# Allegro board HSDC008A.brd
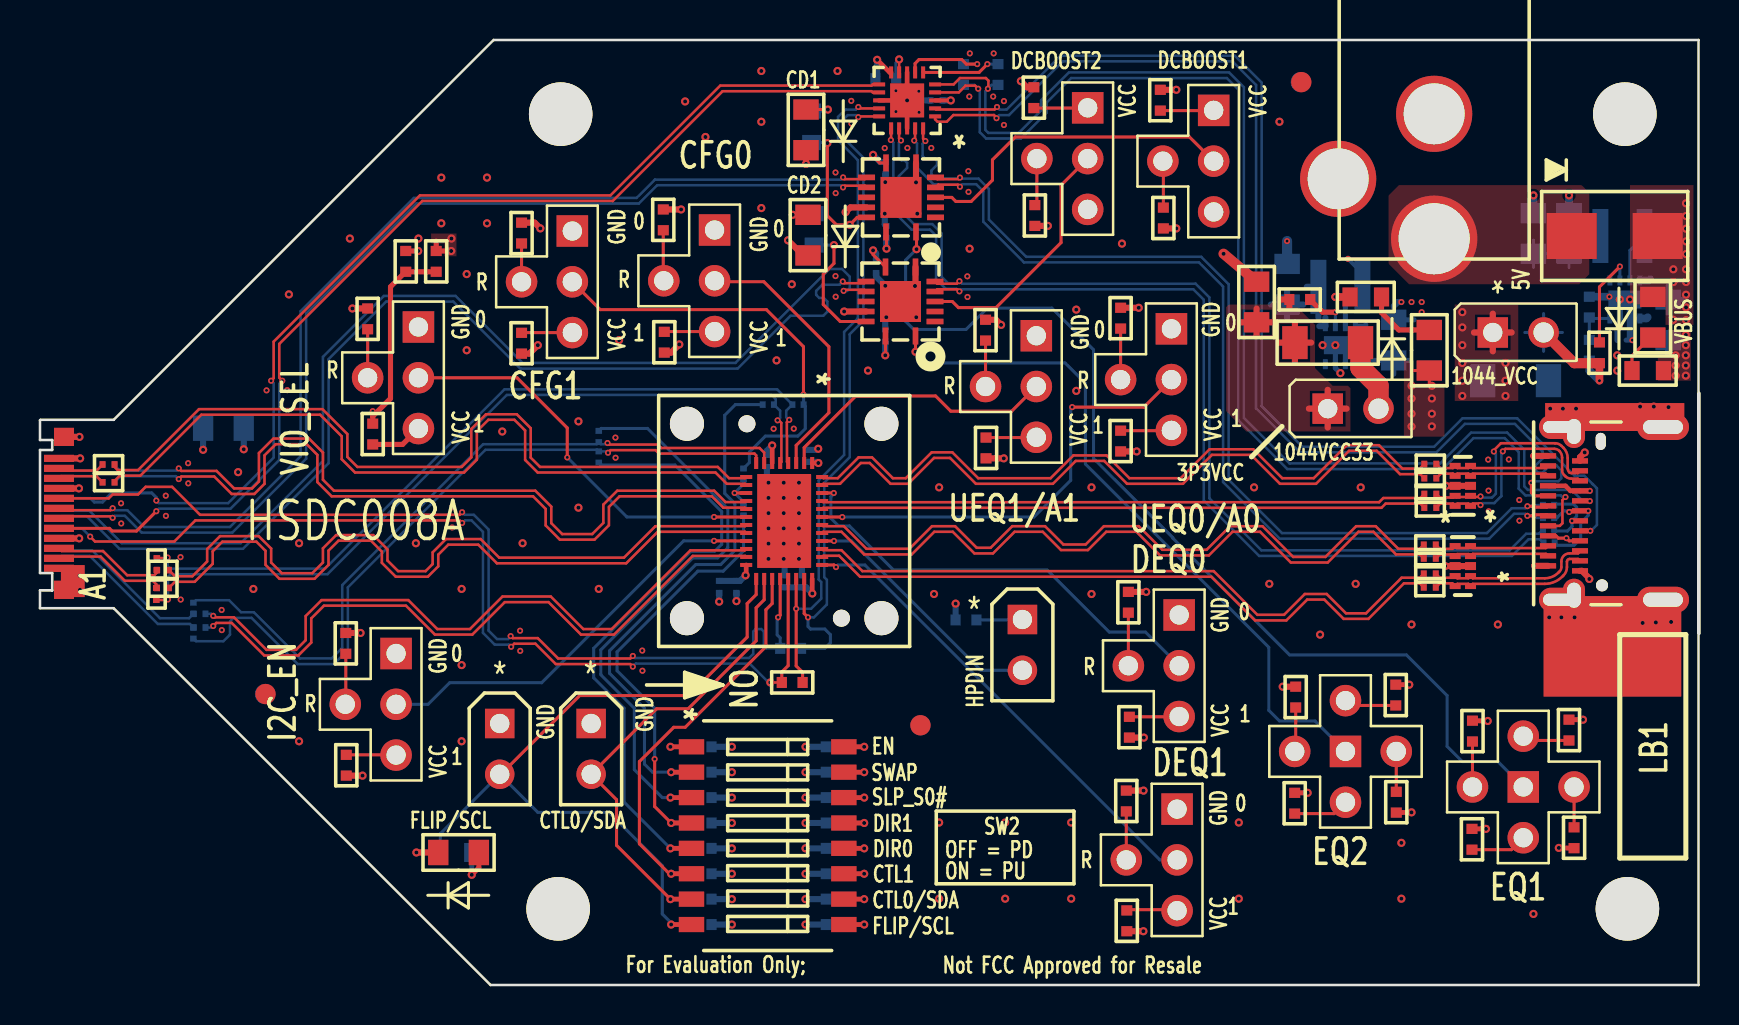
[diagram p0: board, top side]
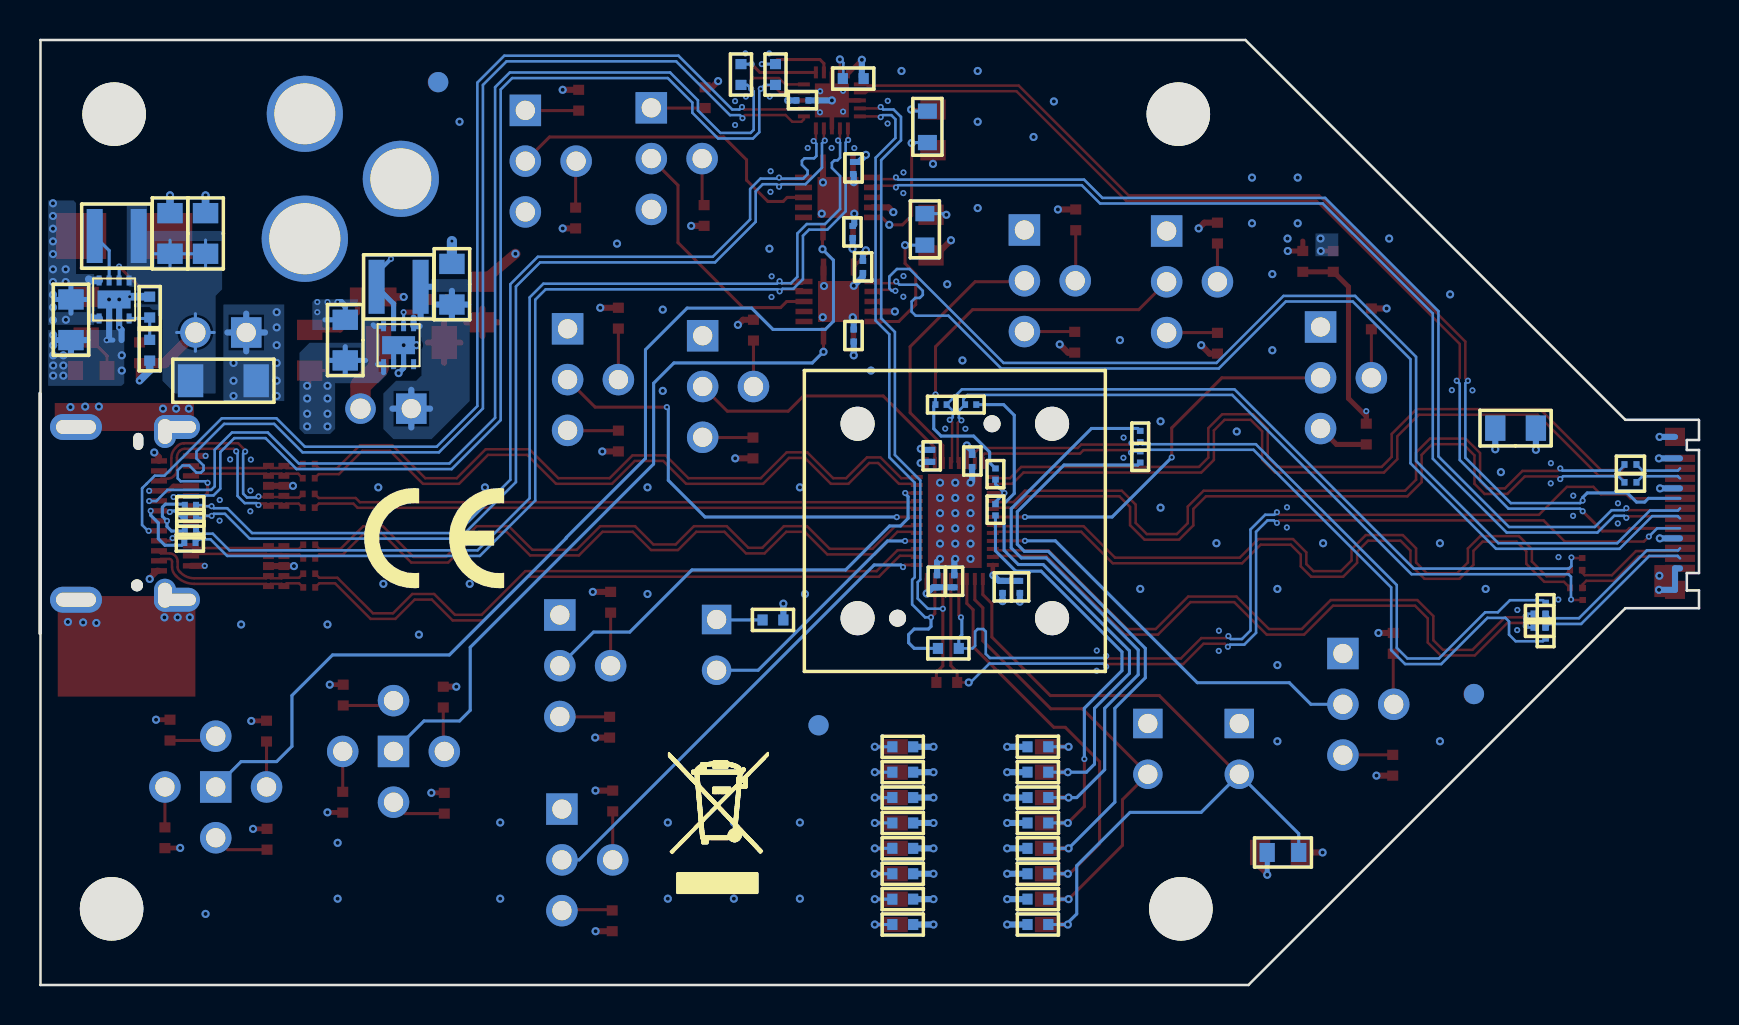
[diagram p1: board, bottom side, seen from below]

Outline 82.95 x 47.27 mm; copper layers: TOP, L2_GND, L3_PWR, L4_PWR, L5_GND, BOTTOM. Coordinates in mm from the lower left corner of the outline.
Outline path: 0,28.24 0.03,28.27 3.68,28.27 22.68,47.27 82.93,47.27 82.93,0 22.53,0 3.68,18.85 0,18.85 0,19.74 0.61,19.74 0.61,19.74 0.61,20.6 0.6,20.61 0,20.61 0,26.76 0.6,26.76 0.61,26.77 0.61,27.25 0.6,27.26 0,27.26 0,28.24

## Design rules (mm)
net group DIFFPAIR0: nets URX2N URX2P
net group DIFFPAIR1: nets UTX1N UTX1P
net group DIFFPAIR2: nets UTX2N UTX2P
net group DIFFPAIR3: nets URX1N URX1P
net group DIFFPAIR4: nets N48836 N48840
net group DIFFPAIR5: nets N48852 N48856
net group DIFFPAIR6: nets N48828 N48832
net group DIFFPAIR7: nets N48844 N48848
net group DIFFPAIR8: nets C_DRX2N C_DRX2P
net group DIFFPAIR9: nets C_DTX2N C_DTX2P
net group DIFFPAIR10: nets C_DTX1N C_DTX1P
net group DIFFPAIR11: nets C_DRX1N C_DRX1P
net group DIFFPAIR12: nets DRX2N DRX2P
net group DIFFPAIR13: nets DTX2N DTX2P
net group DIFFPAIR14: nets DTX1N DTX1P
net group DIFFPAIR15: nets DRX1N DRX1P
net group DIFFPAIR16: nets UDM1 UDP1
net group DIFFPAIR17: nets AUXN AUXP
net group DIFFPAIR18: nets DDM1 DDP1
net group DIFFPAIR19: nets DDM2 DDP2
net group DIFFPAIR20: nets UDM2 UDP2
net group DIFFPAIR21: nets DIR0_URX1P SLP_URX1N
net group DIFFPAIR22: nets CFG1_UTX1N SWAP_UTX1P
net group DIFFPAIR23: nets CC1 CC2
net group DIFFPAIR24: nets C_CC1 C_CC2
net group DIFFPAIR25: nets SBU1 SBU2
net group DIFFPAIR26: nets C_SBU1 C_SBU2
nets with their own width: min track width 0.305; nets 3P3VCC 5V_IN 1044_VCC GND

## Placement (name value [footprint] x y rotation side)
C1  220nF  [C0201]  3.43 26.04 0 top
C2  220nF  [C0201]  3.43 25.15 0 top
C3  220nF  [C0201]  3.43 26.04 0 bottom
C4  220nF  [C0201]  3.43 25.15 0 bottom
C5  220nF  [C0201]  6.15 20.75 0 top
C6  220nF  [C0201]  6.15 19.86 0 top
C7  220nF  [C0201]  7.98 18.57 0 bottom
C8  220nF  [C0201]  7.98 17.88 0 bottom
C9  220nF  [C0201]  69.52 26.06 0 top
C10  220nF  [C0201]  69.52 25.35 0 top
C11  220nF  [C0201]  69.52 24.56 0 top
C12  220nF  [C0201]  69.52 23.88 0 top
C13  220nF  [C0201]  69.49 22.02 0 top
C14  220nF  [C0201]  69.49 21.34 0 top
C15  220nF  [C0201]  69.49 20.57 0 top
C16  220nF  [C0201]  69.49 19.89 0 top
C17  10uF  [0805]  9.17 27.85 180 bottom
C18  1uF  [C0201]  36.35 26.21 270 bottom
C19  1uF  [C0201]  33.96 19.91 270 bottom
C20  1uF  [C0201]  38.1 20.19 90 bottom
C21  0.1uF  [C0201]  38.35 26.47 90 bottom
C22  0.1uF  [C0201]  34.82 19.91 270 bottom
C23  0.1uF  [C0201]  37.24 20.19 90 bottom
C24  10uF  [0805]  74.68 37.59 90 bottom
C25  10uF  [0805]  81.41 33.27 270 bottom
C26  22uF  [0805]  76.45 37.59 90 bottom
C27  0.1uF  [C0201]  44.83 44.25 180 bottom
C28  0.1uF  [C0201]  42.32 37.67 90 bottom
C29  0.1uF  [C0201]  42.29 40.87 270 bottom
C30  0.1uF  [C0201]  5.84 21.06 90 top
C31  0.1uF  [C0201]  5.82 19.56 270 top
C32  0.1uF  [C0201]  42.27 32.49 90 bottom
C33  0.1uF  [C0201]  41.81 35.92 270 bottom
C34  10uF  [0805]  60.83 34.16 90 top
C35  10uF  [0805]  67.69 32.26 90 bottom
C36  22uF  [0805]  62.36 35.05 90 bottom
D1  SCHOTTKY  [DIODE_SMB]  78.74 37.47 180 top
D2  Green  [LED0805]  80.64 33.4 90 top
D3  Green  [LED0805]  38.3 42.77 90 top
D4  Green  [LED0805]  20.93 6.63 0 top
D5  Green  [LED0805]  38.4 37.51 90 top
D6  Green  [LED0805]  69.47 31.75 270 top
J1  CON02  [HDR_THVT_1X2_100_M]  27.56 13.08 0 top
J2  CON02  [HDR_THVT_1X2_100_M]  22.99 13.08 0 top
J3  CON02  [HDR_THVT_1X2_100_M]  49.12 18.28 0 top
J4  CON02  [BERG1X2]  72.64 32.64 90 top
J5  DC_PWR_JACK  [PJ-202AH]  69.71 37.33 180 top
J6  CON02  [BERG1X2]  64.39 28.83 90 top
JMP1  4 Pin-T Berg Jumper  [BERG2X3TEE]  52.39 43.88 270 top
JMP2  4 Pin-T Berg Jumper  [BERG2X3TEE]  56.86 8.8 270 top
JMP3  4 Pin-T Berg Jumper  [BERG2X3TEE]  56.96 18.51 270 top
JMP4  4 Pin-T Berg Jumper  [BERG2X3TEE]  49.82 32.48 270 top
JMP5  4 Pin-T Berg Jumper  [BERG2X3TEE]  56.57 32.82 270 top
JMP6  4 Pin-T Berg Jumper  [BERG2X3TEE]  26.62 37.71 270 top
JMP7  4 Pin-T Berg Jumper  [BERG2X3TEE]  33.73 37.76 270 top
JMP8  4 Pin-T Berg Jumper  [BERG2X3TEE]  18.92 32.91 270 top
JMP9  4 Pin-T Berg Jumper  [BERG2X3TEE]  17.81 16.58 270 top
JMP10  5Pin-T Berg Jumper  [BERG3X3_PLUS]  74.17 9.91 0 top
JMP11  4 Pin-T Berg Jumper  [BERG2X3TEE]  58.69 43.75 270 top
JMP12  5Pin-T Berg Jumper  [BERG3X3_PLUS]  65.28 11.68 0 top
L1  1uH  [IND_NR3015]  79.12 37.47 180 bottom
L2  1uH  [IND_NR3015]  65.02 34.92 180 bottom
NOREF  -  [unnamed]  26.04 43.56 0 top
NOREF#2  -  [#2]  88.9 38.1 0 top
NOREF#3  -  [unnamed]  25.91 3.81 0 top
NOREF#4  -  [unnamed]  44.03 12.99 0 top
NOREF#5  -  [#2]  82.93 -0.03 90 top
NOREF#6  -  [#2]  0 0 0 top
NOREF#7  -  [unnamed]  63.07 45.16 0 top
NOREF#8  -  [unnamed]  79.25 43.56 0 top
NOREF#9  -  [unnamed]  79.38 3.81 0 top
NOREF#10  -  [#2]  0 18.85 0 top
NOREF#11  -  [unnamed]  11.28 14.55 0 top
NOREF#12  -  [#2]  -3.81 -69.85 0 top
NOREF#13  -  [#2]  49.02 8.64 180 bottom
NOREF#14  -  [unnamed]  63.04 45.16 180 bottom
NOREF#15  -  [unnamed]  44.03 12.99 180 bottom
NOREF#16  -  [unnamed]  11.25 14.55 180 bottom
NOREF#17  -  [#2]  63.25 22.35 180 bottom
NOREF#18  -  [#2]  22.53 24.08 180 bottom
P1  Wurth 632712000021  [USB-C_SMRT_632_712_000_B6_B7]  0 23.59 90 top
P2  JAE DX07S024JJ2  [USB-C_SMRT_DX07S024JJ2]  78.11 23.59 90 top
R1  * 0 Ohm  [R0402]  37.53 16.84 0 bottom
R2  * 0 Ohm  [R0402]  37.61 15.13 0 top
R3  1K  [R0402]  39.81 11.92 0 bottom
R4  1K  [R0402]  39.81 10.65 0 bottom
R5  1K  [R0402]  39.81 9.38 0 bottom
R6  1K  [R0402]  39.81 8.11 0 bottom
R7  1K  [R0402]  39.81 6.84 0 bottom
R8  1K  [R0402]  39.81 5.57 0 bottom
R9  1K  [R0402]  39.81 4.3 0 bottom
R10  1K  [R0402]  39.81 3.03 0 bottom
R11  100K  [R0402]  33.06 11.92 0 bottom
R12  100K  [R0402]  33.06 10.65 0 bottom
R13  100K  [R0402]  33.06 9.38 0 bottom
R14  100K  [R0402]  33.06 8.11 0 bottom
R15  100K  [R0402]  33.06 6.84 0 bottom
R16  100K  [R0402]  33.06 5.57 0 bottom
R17  100K  [R0402]  33.06 4.3 0 bottom
R18  100K  [R0402]  33.06 3.03 0 bottom
R19  1K  [R0402]  54.34 3.21 270 top
R20  1K  [R0402]  54.47 12.9 270 top
R21  20K  [R0402]  54.32 9.2 90 top
R22  39.2K  [R0402]  77.47 33.91 90 bottom
R23  20K  [R0402]  54.42 19.14 90 top
R24  1K  [R0402]  47.3 26.86 270 top
R25  1K  [R0402]  54.03 27.21 270 top
R26  1K  [R0402]  46.3 18.26 180 bottom
R27  20K  [R0402]  47.28 32.76 90 top
R28  20K  [R0402]  54.03 33.36 90 top
R29  1K  [R0402]  24.08 32.1 270 top
R30  1K  [R0402]  31.22 32.15 270 top
R31  20K  [R0402]  24.08 37.61 90 top
R32  20K  [R0402]  31.17 38.27 90 top
R33  1K  [R0402]  16.64 27.56 90 top
R34  20K  [R0402]  16.38 33.32 90 top
R35  1K  [R0402]  15.32 10.99 270 top
R36  178K  [R0402]  77.47 31.75 90 bottom
R37  20K  [R0402]  15.29 17.09 90 top
R38  0  [R0402]  19.81 36.2 270 top
R39  178K  [R0402]  77.98 31.62 270 top
R40  0 Ohm  [R1206]  73.79 30.23 180 bottom
R41  330 Ohm  [R0603]  80.39 30.73 0 top
R42  100K  [R0402]  42.29 45.34 0 bottom
R43  0  [R0402]  46.18 45.54 270 bottom
R44  0  [R0402]  47.9 45.54 270 bottom
R45  200  [R0402]  76.71 7.37 270 top
R46  1.5K  [R0402]  76.45 12.75 90 top
R47  3.9K  [R0402]  71.63 12.7 90 top
R48  6.2K  [R0402]  71.6 7.29 90 top
R49  20K  [R0402]  56.02 44.26 90 top
R50  20K  [R0402]  56.17 38.36 270 top
R51  0  [R0402]  18.29 36.2 270 top
R52  330 Ohm  [R0603]  66.29 34.42 180 top
R53  0  [R0201]  7.67 17.6 270 bottom
R54  0  [R0201]  7.67 18.85 90 bottom
R55  178K  [R0402]  62.99 34.29 180 top
R56  0 Ohm  [R1206]  64.39 32.13 0 top
R57  20K  [R0402]  49.75 38.49 270 top
R58  20K  [R0402]  49.7 44.38 90 top
R59  6.2K  [R0402]  62.74 9.09 90 top
R60  3.9K  [R0402]  62.79 14.4 90 top
R61  0  [R0201]  27.94 26.42 90 bottom
R62  0  [R0201]  27.94 27.43 270 bottom
R63  0  [R0201]  36.42 29.03 0 bottom
R64  0  [R0201]  37.9 29.03 180 bottom
R65  0  [R0201]  35.18 23.77 90 bottom
R66  0  [R0201]  35.18 25.55 270 bottom
R67  75  [R0603]  38.58 42.93 90 bottom
R68  75  [R0603]  20.8 6.63 0 bottom
R69  0  [R0201]  75.44 24 0 bottom
R70  0  [R0201]  75.44 23.37 0 bottom
R71  0  [R0201]  75.46 22.12 0 bottom
R72  0  [R0201]  75.44 22.78 0 bottom
R73  75  [R0603]  38.71 37.8 90 bottom
R74  200  [R0402]  67.82 9.14 270 top
R75  1.5K  [R0402]  67.79 14.5 90 top
SW1  8-POS 50-MIL SMT  [SW_SMVT_SPST_TDA08]  36.39 7.47 270 top
U1  TUSB1044  [SKT_IRONWOOD_C14861_QFN-40]  37.21 23.21 270 top
U2  TPS62080DSGT  [DSG]  79.25 34.29 90 bottom
U3  TPD6S300  [RUK0020B]  43.36 44.25 180 top
U4  TPD4E02B04  [DQA0010A]  71.15 20.95 0 top
U5  TPD4E02B04  [DQA0010A]  71.15 24.97 180 top
U6  TUSB212  [RGY_S-PVQFN-N14]  43.05 39.4 90 top
U7  TUSB212  [RGY_S-PVQFN-N14]  43.03 34.19 90 top
U8  TPS62082DSGT  [DSG]  65.02 32 90 bottom

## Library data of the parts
C1-C16 = cc0201
C17 C24 C34 = CAP
C18-C23 C27-C33 = cc0402
C25 C26 C35 C36 = CAP NP
D1 = SCHOTTKY
D2-D6 = Green LED_2
J1-J4 = CON02_2
J5 = 6140046600_DC_PWR_JACK
J6 = CON02_1
JMP1-JMP9 JMP11 = 4 Pin-T Berg Jumper
JMP10 JMP12 = 5Pin-T Berg Jumper
L1 L2 = INDUCTOR
P1 = Type C Plug_1
P2 = TypeC_JAE_TopMNT_1
R1-R21 R23-R35 R37 R39 R55 = r0402
R22 R36 R38 R42-R51 R53 R54 R57-R75 = R
R40 R56 = r1206
R41 R52 = r0603
SW1 = SW DIP-8/SM_0
U1 = TUSB1044RNQ_0
U2 U8 = TPS62082
U3 = TPD8S300_0
U4 U5 = TPD4E02B04_0
U6 U7 = TUSB213_0

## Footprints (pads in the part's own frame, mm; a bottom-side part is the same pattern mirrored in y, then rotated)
0805
  rect 1.016x1.27 smd: 1(-1.016,0) 2(1.016,0)
BERG1X2
  rect 1.524x1.524 hole 0.965: 1(0,0)
  round 1.524 hole 1.016: 2(0,-2.54)
BERG2X3TEE
  rect 1.575x1.575 hole 0.965: 1(0,0)
  round 1.575 hole 0.965: 2(2.54,0) 3(5.08,0) 4(2.54,-2.54)
BERG3X3_PLUS
  rect 1.575x1.575 hole 0.965: 1(0,0)
  round 1.575 hole 0.965: 2(2.54,0) 3(0,2.54) 4(-2.54,0) 5(0,-2.54)
C0201
  rect 0.3x0.33 smd: 1(-0.3,0) 2(0.3,0)
DIODE_SMB
  rect 2.5x2.3 smd: 1(-2.15,0) 2(2.15,0)
DQA0010A
  rect 0.55x0.3 smd: 1(-0.385,1) 2(-0.385,0.5) 4(-0.385,-0.5) 5(-0.385,-1) 6(0.385,-1) 7(0.385,-0.5) 9(0.385,0.5) 10(0.385,1)
  rect 0.55x0.4 smd: 3(-0.385,0) 8(0.385,0)
DSG
  rect 0.5x0.25 smd: 1(-0.95,0.75) 2(-0.95,0.25) 3(-0.95,-0.25) 4(-0.95,-0.75) 5(0.95,-0.75) 6(0.95,-0.25) 7(0.95,0.25) 8(0.95,0.75)
  rect 0.9x1.65 smd: 9(0,0)
HDR_THVT_1X2_100_M
  rect 1.473x1.473 hole 0.965: 1(0,0)
  round 1.473 hole 0.965: 2(0,-2.54)
IND_NR3015
  rect 0.8x2.7 smd: 1(-1.1,0) 2(1.1,0)
LED0805
  rect 1.016x1.27 smd: 1(-1.016,0) 2(1.016,0)
PJ-202AH
  round 4.318 hole 3.556: 1(0,0)
  round 3.81 hole 3.048: 2(4.801,-2.997) 3(0,-6.248)
R0201
  rect 0.3x0.33 smd: 1(-0.285,0) 2(0.275,0)
R0402
  rect 0.51x0.55 smd: 1(-0.52,0) 2(0.52,0)
R0603
  rect 0.76x0.95 smd: 1(-0.787,0) 2(0.787,0)
R1206
  rect 1.27x1.65 smd: 1(-1.64,0) 2(1.64,0)
RGY_S-PVQFN-N14
  rect 0.85x0.28 smd: 1(-1.725,-0.75) 7(1.725,-0.75) 8(1.725,0.75) 14(-1.725,0.75)
  rect 0.28x0.85 smd: 2(-1,-1.725) 3(-0.5,-1.725) 4(0,-1.725) 5(0.5,-1.725) 6(1,-1.725) 9(1,1.725) 10(0.5,1.725) 11(0,1.725) 12(-0.5,1.725) 13(-1,1.725)
  rect 2.05x2.05 smd: 15(0,0)
RUK0020B
  rect 0.6x0.2 smd: 1(-1.4,0.8) 2(-1.4,0.4) 3(-1.4,0) 4(-1.4,-0.4) 5(-1.4,-0.8) 11(1.4,-0.8) 12(1.4,-0.4) 13(1.4,0) 14(1.4,0.4) 15(1.4,0.8)
  rect 0.2x0.6 smd: 6(-0.8,-1.4) 7(-0.4,-1.4) 8(0,-1.4) 9(0.4,-1.4) 10(0.8,-1.4) 16(0.8,1.4) 17(0.4,1.4) 18(0,1.4) 19(-0.4,1.4) 20(-0.8,1.4)
  rect 1.7x1.7 smd: 21(0,0)
SKT_IRONWOOD_C14861_QFN-40
  round 1.702 hole 1.702 unplated: (-4.863,4.863) (-4.863,-4.863) (4.863,4.863) (4.863,-4.863)
  round 0.85 hole 0.85 unplated: (-4.863,-1.863) (4.863,2.863)
  rect 0.6x0.2 smd: 1(-2.9,1.4) 2(-2.9,1) 3(-2.9,0.6) 4(-2.9,0.2) 5(-2.9,-0.2) 6(-2.9,-0.6) 7(-2.9,-1) 8(-2.9,-1.4) 21(2.9,-1.4) 22(2.9,-1) 23(2.9,-0.6) 24(2.9,-0.2) 25(2.9,0.2) 26(2.9,0.6) 27(2.9,1) 28(2.9,1.4)
  rect 0.2x0.6 smd: 9(-2.2,-1.9) 10(-1.8,-1.9) 11(-1.4,-1.9) 12(-1,-1.9) 13(-0.6,-1.9) 14(-0.2,-1.9) 15(0.2,-1.9) 16(0.6,-1.9) 17(1,-1.9) 18(1.4,-1.9) 19(1.8,-1.9) 20(2.2,-1.9) 29(2.2,1.9) 30(1.8,1.9) 31(1.4,1.9) 32(1,1.9) 33(0.6,1.9) 34(0.2,1.9) 35(-0.2,1.9) 36(-0.6,1.9) 37(-1,1.9) 38(-1.4,1.9) 39(-1.8,1.9) 40(-2.2,1.9)
  rect 4.699x2.692 smd: 41(0,0)
SW_SMVT_SPST_TDA08
  rect 0.762x1.27 smd: 1(-4.445,-3.81) 2(-3.175,-3.81) 3(-1.905,-3.81) 4(-0.635,-3.81) 5(0.635,-3.81) 6(1.905,-3.81) 7(3.175,-3.81) 8(4.445,-3.81) 9(4.445,3.81) 10(3.175,3.81) 11(1.905,3.81) 12(0.635,3.81) 13(-0.635,3.81) 14(-1.905,3.81) 15(-3.175,3.81) 16(-4.445,3.81)
unnamed
  round 3.175 hole 3.175 unplated: (0,0)
USB-C_SMRT_632_712_000_B6_B7
  rect 0.35x1.5 smd: A1(-2.75,-0.95) A2(-2.25,-0.95) A3(-1.75,-0.95) A4(-1.25,-0.95) A5(-0.75,-0.95) A6(-0.25,-0.95) A7(0.25,-0.95) A8(0.75,-0.95) A9(1.25,-0.95) A10(1.75,-0.95) A11(2.25,-0.95) A12(2.75,-0.95) B1(2.75,-0.95) B2(2.25,-0.95) B3(1.75,-0.95) B4(1.25,-0.95) B5(0.75,-0.95) B6(0.25,-0.95) B7(-0.25,-0.95) B8(-0.75,-0.95) B9(-1.25,-0.95) B10(-1.75,-0.95) B11(-2.25,-0.95) B12(-2.75,-0.95)
  rect 0.9x1 smd: C1(-3.825,-1.2) C2(3.825,-1.2) C3(-3.825,-1.2) C4(3.825,-1.2)
USB-C_SMRT_DX07S024JJ2
  round 0.6 hole 0.6 unplated: (-3.6,0)
  oval 0.85x0.5 hole 0.85x0.5 unplated: (3.6,0.065)
  oval 1.65x1.1 hole 1.25x0.7: 1(-4.095,1.4) 5(4.095,1.4)
  oval 1.2x2.3 hole 0.6x1.9: 2(-4.32,2) 6(4.32,2)
  oval 1.3x2.6 hole 0.7x2: 3(-4.32,-3.05) 4(4.32,-3.05)
  rect 0.27x0.81 smd: A1(-2.625,2.7) A2(-2.125,2.7) A3(-1.625,2.7) A4(-1.125,2.7) A5(-0.625,2.7) A6(-0.125,2.7) A7(0.375,2.7) A8(0.875,2.7) A9(1.375,2.7) A10(1.875,2.7) A11(2.375,2.7) A12(2.875,2.7)
  rect 0.27x0.8 smd: B1(2.625,1.1) B2(2.125,1.1) B3(1.625,1.1) B4(1.125,1.1) B5(0.625,1.1) B6(0.125,1.1) B7(-0.375,1.1) B8(-0.875,1.1) B9(-1.375,1.1) B10(-1.875,1.1) B11(-2.375,1.1) B12(-2.875,1.1)

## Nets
5V_IN: D1.2(A) J5.1(+IN)
GND: C17.2(B) C18.2 C19.2 C20.2 C21.2 C22.2 C23.2 C24.2(B) C25.2 C26.2 C27.2 C28.2 C29.2 C32.2 C33.2 C34.2(B) C35.2 C36.2 D3.1(CATHODE) D4.1(CATHODE) D5.1(CATHODE) J1.1(P1) J2.1(P1) J5.2(GND) J5.3(GND#3) JMP2.1 JMP3.1 JMP4.1 JMP5.1 JMP6.1 JMP7.1 JMP8.1 JMP9.1 P1.A1(GND#A1) P1.A12(GND#A12) P1.B1(GND#B1) P1.B12(GND#B12) P1.C1(GND#C1) P1.C2(GND#C2) P1.C3(GND#C3) P1.C4(GND#C4) P2.1(CHASSIS1) P2.2(CHASSIS2) P2.3(CHASSIS3) P2.4(CHASSIS4) P2.5(CHASSIS5) P2.6(CHASSIS6) P2.A1(GND1) P2.A12(GND2) P2.B1(GND3) P2.B12(GND4) R11.2 R12.2 R13.2 R14.2 R15.2 R16.2 R17.2 R18.2 R21.2 R22.2 R23.2 R27.2 R28.2 R31.2 R32.2 R34.2 R37.2 R41.2 R45.2 R46.2 R47.2 R48.2 R50.2 R52.2 R57.2 R59.2 R60.2 R74.2 R75.2 U1.41(PAD/GND) U2.2(GND) U2.3(MODE) U2.9(PWPD) U3.8(GND1) U3.13(GND2) U3.18(GND3) U3.21(PAD) U4.3(GND1) U4.8(GND2) U5.3(GND1) U5.8(GND2) U6.7(GND) U6.15(PAD) U7.7(GND) U7.15(PAD) U8.2(GND) U8.3(MODE) U8.9(PWPD)
VBUS: C17.1(A) C25.1 C35.1 D1.1(K) D2.2(ANODE) D6.2(ANODE) P1.A4(VBUS#A4) P1.A9(VBUS#A9) P1.B4(VBUS#B4) P1.B9(VBUS#B9) P2.A4(VBUS1) P2.A9(VBUS2) P2.B4(VBUS3) P2.B9(VBUS4) U2.1(EN) U2.8(VIN) U8.1(EN) U8.8(VIN)
2P5VCC: C24.1(A) C26.1 J4.2(P2) L1.2 R36.1 R39.2 R40.1 U2.5(VOS)
3P3VCC: C34.1(A) C36.1 J6.1(P2) L2.2 R55.2 R56.1 U8.5(VOS)
1044_VCC: C18.1 C19.1 C20.1 C21.1 C22.1 C23.1 J4.1(P1) R3.1 R4.1 R5.1 R6.1 R7.1 R8.1 R9.1 R10.1 R19.2 R20.2 R24.2 R25.2 R26.2 R29.2 R30.2 R35.2 R40.2 R42.1 R49.2 R51.1 R58.2 U1.1(VCC#1) U1.6(VCC#6) U1.20(VCC#20) U1.28(VCC#28) U3.10(VPWR) U6.12(VCC) U7.12(VCC)
1044_VCC33: J6.2(P1) R38.1 R56.2
AUXN: P1.B8(SBU2) R2.1 U1.25(AUXN)
AUXP: P1.A8(SBU1) R1.1 U1.24(AUXP)
C_CC1: P2.A5(CC1) R43.2 U3.4(C_CC1)
C_CC2: P2.B5(CC2) R44.2 U3.5(C_CC2)
C_DRX1N: C15.1 U1.31(RX1N)
C_DRX1P: C16.1 U1.30(RX1P)
C_DRX2N: C10.1 U1.39(RX2N)
C_DRX2P: C9.1 U1.40(RX2P)
C_DTX1N: C13.1 U1.34(TX1N)
C_DTX1P: C14.1 U1.33(TX1P)
C_DTX2N: C12.1 U1.36(TX2N)
C_DTX2P: C11.1 U1.37(TX2P)
C_SBU1: P2.A8(SBU1) U3.1(C_SBU1)
C_SBU2: P2.B8(SBU2) U3.2(C_SBU2)
CC1: P1.A5(CC1) U3.12(CC1)
CC2: P1.B5(CC2) U3.11(CC2)
CD1: R67.1 U6.13(SCL)
CD2: R73.1 U7.13(SCL)
CFG0: JMP7.2 U1.3(SSEQ1)
CFG1: JMP6.2 R64.1 R66.1
CFG1_UTX1N: C30.2 R64.2 U1.4(SSRXN)
CTL0/SDA: J1.2(P2) R17.1 SW1.7(A7) U1.22(CTL0/SDA)
CTL1: R16.1 SW1.6(A6) U1.23(CTL1/HPDIN)
DC_BOOST1: JMP11.2 U6.4(ENA_HS)
DC_BOOST2: JMP1.2 U7.4(ENA_HS)
DDM1: P2.A7(DN1) R69.1 U3.20(D1) U6.6(D2M)
DDM2: R72.1 U3.17(D3) U7.6(D2M)
DDP1: P2.A6(DP1) R70.1 U3.19(D2) U6.5(D2P)
DDP2: R71.1 U3.16(D4) U7.5(D2P)
DEQ0: JMP3.2 U1.38(EQ0)
DEQ1: JMP2.2 U1.29(CAD_SNK)
DIR0: R15.1 R61.1 SW1.5(A5)
DIR0_URX1P: R53.2 R61.2 U1.8(SSTXP)
DIR1: R14.1 R65.1 SW1.4(A4)
DRX1N: C15.2 P2.B10(SSRXN1) U4.4(IO3) U4.7(NC3)
DRX1P: C16.2 P2.B11(SSRXP1) U4.5(IO4) U4.6(NC4)
DRX2N: C10.2 P2.A10(SSRXN2) U5.4(IO3) U5.7(NC3)
DRX2P: C9.2 P2.A11(SSRXP2) U5.5(IO4) U5.6(NC4)
DTX1N: C13.2 P2.A3(SSTXN1) U4.1(IO1) U4.10(NC1)
DTX1P: C14.2 P2.A2(SSTXP1) U4.2(IO2) U4.9(NC2)
DTX2N: C12.2 P2.B3(SSTXN2) U5.1(IO1) U5.10(NC1)
DTX2P: C11.2 P2.B2(SSTXP2) U5.2(IO2) U5.9(NC2)
EN: R11.1 SW1.1(A1)
EQ1: JMP10.1 U6.1(EQ)
EQ2: JMP12.1 U7.1(EQ)
FLIP/SCL: J2.2(P2) R18.1 R68.1 SW1.8(A8) U1.21(FLIP/SCL)
HPDIN: J3.2(P2) U1.32(HPDIN)
I2C_EN: JMP9.2 U1.17(I2C_EN)
SBU1: R1.2 U1.27(SBU1) U3.15(SBU1)
SBU2: R2.2 U1.26(SBU2) U3.14(SBU2)
SLP_S0#: R13.1 R62.1 SW1.3(A3)
SLP_URX1N: R54.2 R62.2 U1.7(SSTXN)
SWAP: R12.1 R63.1 SW1.2(A2)
SWAP_UTX1P: C31.2 R63.2 U1.5(SSRXP)
U2_PG: R39.1 U2.6(PG)
U2_SW: L1.1 U2.7(SW)
U8_PG: R55.1 U8.6(PG)
U8_SW: L2.1 U8.7(SW)
UDM1: P1.A7(DN1) U6.9(D1M)
UDM2: P1.B7(DN2) U7.9(D1M)
UDP1: P1.A6(DP1) U6.10(D1P)
UDP2: P1.B6(DP2) U7.10(D1P)
UEQ0/A0: JMP5.2 U1.35(EQ1)
UEQ1/A1: JMP4.2 U1.2(DPEQ1)
URX1N: C7.1 P1.B10(SSRXN1) R54.1
URX1P: C8.1 P1.B11(SSRXP1) R53.1
URX2N: C2.1 P1.A10(SSRXN2)
URX2P: C1.1 P1.A11(SSRXP2)
UTX1N: C5.1 C30.1 P1.A3(SSTXN1)
UTX1P: C6.1 C31.1 P1.A2(SSTXP1)
UTX2N: C4.1 P1.B3(SSTXN2)
UTX2P: C3.1 P1.B2(SSTXP2)
VIO_SEL: JMP8.2 U1.14(DPEQ0/A1)
N06058: R3.2 SW1.16(B1)
N06065: R4.2 SW1.15(B2)
N06072: R5.2 SW1.14(B3)
N06079: R6.2 SW1.13(B4)
N06086: R7.2 SW1.12(B5)
N06093: R8.2 SW1.11(B6)
N06100: R9.2 SW1.10(B7)
N06107: R10.2 SW1.9(B8)
N06374: JMP2.3 R19.1
N06386: JMP2.4 R21.1
N06671: JMP4.3 R24.1
N06683: JMP4.4 R27.1
N06999: JMP3.3 R20.1
N07011: JMP3.4 R23.1
N07344: JMP5.3 R25.1
N07356: JMP5.4 R28.1
N08045: R33.2 R38.2 R51.2
N08061: JMP8.3 R33.1
N08073: JMP8.4 R34.1
N08437: JMP9.3 R35.1
N08449: JMP9.4 R37.1
N08820: JMP7.3 R30.1
N08832: JMP7.4 R32.1
N09158: J3.1(P1) R26.1
N09488: JMP6.3 R29.1
N09500: JMP6.4 R31.1
N15413: D2.1(CATHODE) R41.1
N35354: JMP10.4 R47.1
N35366: JMP10.2 R45.1
N35378: JMP10.3 R46.1
N35403: JMP10.5 R48.1
N36817: JMP11.1 R49.1
N36900: JMP11.4 R50.1
N48828: C1.2 U1.9(DP0P)
N48832: C2.2 U1.10(DP0N)
N48836: C3.2 U1.12(DP1P)
N48840: C4.2 U1.13(DP1N)
N48844: C5.2 U1.15(DP2P)
N48848: C6.2 U1.16(DP2N)
N48852: C7.2 U1.18(DP3P)
N48856: C8.2 U1.19(DP3N)
N48872: P2.B6(DP2) R70.2 R71.2
N48884: P2.B7(DN2) R69.2 R72.2
N50484: R42.2 U3.9(F\L\T\)
N50648: C27.1 U3.3(VBIAS)
N50826: R43.1 U3.7(RPD_G1)
N50830: R44.1 U3.6(RPD_G2)
N51380: C28.1 U6.14(RSTN)
N51484: C29.1 U6.8(VREG)
N69843: R65.2 R66.2 U1.11(SSEQ0/A0)
N74477: D3.2(ANODE) R67.2
N74875: D4.2(ANODE) R68.2
N79063: C32.1 U7.14(RSTN)
N79147: C33.1 U7.8(VREG)
N79572: D5.2(ANODE) R73.2
N80259: JMP12.4 R60.1
N80287: JMP12.2 R74.1
N80299: JMP12.3 R75.1
N80319: JMP12.5 R59.1
N80694: JMP1.1 R58.1
N80722: JMP1.4 R57.1
N151432: D6.1(CATHODE) R52.1
N157347: R22.1 R36.2 U2.4(FB)

Pads without a net: JMP1 3; JMP11 3; U6 2 3 11; U7 2 3 11; U8 4

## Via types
v1: diameter 0.305, hole 0.152, TOP to BOTTOM, 138 vias
v2: diameter 0.406, hole 0.203, TOP to BOTTOM, 250 vias

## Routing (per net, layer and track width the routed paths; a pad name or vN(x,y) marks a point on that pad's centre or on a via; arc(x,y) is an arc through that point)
GND: length 220.4
  TOP w0.229: U3.13 v2(43.36,44.25) ; v2(43.36,44.25) U3.8 ; v2(43.36,44.25) U3.18
  TOP w0.241: R45.2 v2(75.95,6.86) ; R47.2 v2(72.39,13.21) ; R75.2 v2(68.47,15.02) ; R74.2 v2(68.58,8.64) ; R48.2 v2(72.3,7.81) ; R46.2 v2(77.15,13.27) ; R59.2 v2(63.39,9.61)
  TOP w0.305: P2.A1 v1(74.72,20.97) ; R34.2 v2(15.62,33.84) ; v2(70.26,20.95) U4.3 U4.8 ; P2.B1 77,26.4 v2(77.24,26.64) ; R60.2 v2(62.14,14.92) ; U7.7 43.78,34.94 U7.15 ; v2(2,19.77) P1.C1 1.2,20.84 P1.A1 ; D5.1 38.16,36.49 v2(37.4,37.25) ; R57.2 v2(50.39,37.97) ; R28.2 v2(54.94,33.88) ; D4.1 v2(18.82,6.63) ; v2(25.02,37.85) 24.73,38.13 R31.2 ; R27.2 47.8,33.28 v2(48.06,33.02) ; v2(77.47,20.31) 77.47,20.35 77.1,20.72 P2.B12 ; P2.A12 v1(74.68,26.47) ; R21.2 v2(55.18,9.72) ; D3.1 v2(38.3,41.07) ; U5.3 U5.8 v2(70.31,24.97) ; U6.7 v2(43.8,40.15) ; P1.C2 v2(1.97,27.42) ; P1.A12 v2(2.01,26.34) ; R50.2 v2(56.82,37.84) ; R32.2 v2(32.06,38.79) ; R23.2 v2(55.31,19.66) ; R37.2 v2(16.03,17.61)
  TOP w0.381: R52.2 v2(64.77,34.42)
  TOP w0.508: 60.83,35.18 v2(59.18,36.58)
  L2_GND w0.305: 27.56,12.17 J1.1 ; J1.1 27.56,14 ; J1.1 26.64,13.08 ; J1.1 28.47,13.08 ; 17.81,15.62 JMP9.1 ; JMP9.1 16.84,16.58 ; JMP9.1 18.77,16.58 ; JMP9.1 17.81,17.55 ; JMP2.1 57.82,8.8 ; JMP2.1 56.86,7.83 ; JMP2.1 56.86,9.76 ; JMP2.1 55.89,8.8 ; 49.82,31.51 JMP4.1 ; JMP4.1 50.79,32.48 ; JMP4.1 49.82,33.44 ; JMP4.1 48.85,32.48 ; JMP7.1 33.73,38.73 ; JMP7.1 33.73,36.8 ; JMP7.1 34.7,37.76 ; JMP7.1 32.77,37.76 ; P2.4 81.16,28.74 ; P2.4 79.68,27.91 ; P2.4 81.16,27.08 ; JMP5.1 56.57,33.79 ; JMP5.1 57.54,32.82 ; JMP5.1 55.61,32.82 ; JMP5.1 56.57,31.86 ; 76.7,26.68 P2.5 ; P2.5 76.7,28.69 ; P2.5 77.43,27.69 ; J2.1 22.99,14 ; J2.1 23.9,13.08 ; J2.1 22.99,12.17 ; J2.1 22.07,13.08 ; J5.2 67,40.33 ; J5.2 64.91,42.41 ; J5.2 64.91,38.24 ; J5.2 62.83,40.33 ; P2.1 77.43,19.5 ; P2.1 76.7,18.49 ; P2.1 76.7,20.5 ; P2.3 81.16,20.1 ; P2.3 79.68,19.27 ; P2.3 81.16,18.44 ; JMP3.1 57.93,18.51 ; JMP3.1 56.96,19.47 ; JMP3.1 56.96,17.54 ; JMP3.1 56,18.51 ; 74.78,19.27 P2.2 ; P2.2 76.11,18.49 ; P2.2 77.43,19.27 ; 74.78,27.91 P2.6 ; P2.6 77.43,27.91 ; P2.6 76.11,28.69 ; JMP6.1 27.58,37.71 ; JMP6.1 26.62,36.75 ; JMP6.1 26.62,38.68 ; JMP6.1 25.65,37.71 ; J5.3 71.8,43.58 ; J5.3 69.71,41.49 ; J5.3 69.71,45.66 ; J5.3 67.63,43.58 ; 17.96,32.91 JMP8.1 ; JMP8.1 19.89,32.91 ; JMP8.1 18.92,31.95 ; JMP8.1 18.92,33.88
  L5_GND w0.305: 76.7,18.49 P2.1 ; P2.1 76.7,20.5 ; P2.1 77.43,19.5 ; 27.56,12.17 J1.1 ; J1.1 28.47,13.08 ; J1.1 26.64,13.08 ; J1.1 27.56,14 ; JMP6.1 27.58,37.71 ; JMP6.1 26.62,36.75 ; JMP6.1 26.62,38.68 ; JMP6.1 25.65,37.71 ; 76.7,26.68 P2.5 ; P2.5 76.7,28.69 ; P2.5 77.43,27.69 ; 74.78,27.91 P2.6 ; P2.6 77.43,27.91 ; P2.6 76.11,28.69 ; J5.3 71.8,43.58 ; J5.3 67.63,43.58 ; J5.3 69.71,41.49 ; J5.3 69.71,45.66 ; 33.73,36.8 JMP7.1 ; JMP7.1 34.7,37.76 ; JMP7.1 33.73,38.73 ; JMP7.1 32.77,37.76 ; J2.1 22.99,14 ; J2.1 22.07,13.08 ; J2.1 22.99,12.17 ; J2.1 23.9,13.08 ; 16.84,16.58 JMP9.1 ; JMP9.1 17.81,17.55 ; JMP9.1 18.77,16.58 ; JMP9.1 17.81,15.62 ; 18.92,31.95 JMP8.1 ; JMP8.1 17.96,32.91 ; JMP8.1 18.92,33.88 ; JMP8.1 19.89,32.91 ; 81.16,18.44 P2.3 ; P2.3 81.16,20.1 ; P2.3 79.68,19.27 ; JMP5.1 57.54,32.82 ; JMP5.1 55.61,32.82 ; JMP5.1 56.57,31.86 ; JMP5.1 56.57,33.79 ; J5.2 67,40.33 ; J5.2 62.83,40.33 ; J5.2 64.91,38.24 ; J5.2 64.91,42.41 ; JMP3.1 57.93,18.51 ; JMP3.1 56.96,19.47 ; JMP3.1 56,18.51 ; JMP3.1 56.96,17.54 ; JMP4.1 49.82,33.44 ; JMP4.1 49.82,31.51 ; JMP4.1 50.79,32.48 ; JMP4.1 48.85,32.48 ; 79.68,27.91 P2.4 ; P2.4 81.16,28.74 ; P2.4 81.16,27.08 ; 56.86,7.83 JMP2.1 ; JMP2.1 57.82,8.8 ; JMP2.1 55.89,8.8 ; JMP2.1 56.86,9.76 ; 76.11,18.49 P2.2 ; P2.2 77.43,19.27 ; P2.2 74.78,19.27
  BOTTOM w0.254: U8.2 65.27,31.75 U8.9 64.77,31.75 U8.3 64.77,30.86 v2(65.02,30.61) ; v1(79.62,32.25) 79.62,32.26 ; 79.62,32.26 79.31,32.26 ; 79.62,32.26 79.5,32.38 ; 68.71,33.27 C35.2 67.69,33.96 ; v2(64.77,32) v2(64.14,32)
  BOTTOM w0.305: 79.5,32.38 U2.2 79.5,34.04 U2.9 79,34.04 U2.3 79,32.9 v1(78.99,32.89) 78.88,32.78 78.88,32.26 ; R16.2 v2(34.59,5.57) ; C18.2 36.35,25.2 v2(36.43,25.13) ; C25.2 82.22,32.26 ; C25.2 81.41,31.57 ; C25.2 80.59,32.26 ; C28.2 42.24,38.04 v2(42.24,38.58) ; C21.2 38.86,26.77 v2(38.91,26.82) ; C19.2 v2(33.96,19.18) ; v1(68.07,34.16) 67.89,34.16 67.69,33.96 ; P1.A1 1.2,20.84 P1.C1 v2(2,19.77) ; R14.2 v2(34.59,8.11) ; P1.A12 v2(2.01,26.34) ; C33.2 41.81,35.43 v2(42.27,34.98) ; R17.2 v2(34.59,4.3) ; R13.2 v2(34.59,9.38) ; C23.2 37.24,21.27 v2(37.19,21.32) ; C17.2 v2(8.16,26.77) ; v2(42.32,33.4) 42.27,33.35 C32.2 ; v2(37.95,21.32) 38.1,21.17 C20.2 ; R18.2 v2(34.59,3.03) ; C29.2 42.27,40.54 v2(42.27,40.16) ; R11.2 v2(34.59,11.92) ; P1.C2 v2(1.97,27.42) ; v2(43.36,44.25) C27.2 ; R12.2 v2(34.59,10.65) ; C22.2 v2(34.82,19.2) ; R15.2 v2(34.59,6.84)
  BOTTOM w0.381: R22.2 v1(78.47,34.43) ; C24.2 v2(74.68,39.5) ; C26.2 v2(76.45,39.5)
  BOTTOM w0.508: C36.2 v1(62.36,37.21)
  vias: v1(4.05,24.09) v1(4.06,23.09) v1(6.29,24.48) v1(6.3,23.47) v1(7.03,21.4) v1(7.04,19.28) v1(7.41,26.1) v1(7.41,25.09) v1(9.08,18.76) v1(9.09,17.75) v1(11.33,29.74) v1(12.36,29.75) v1(20.6,23.89) v1(20.61,22.89) v1(24.01,17.72) v1(24.01,16.71) v1(28.77,27.38) v1(28.78,26.37) v1(30.11,16.73) v1(30.12,15.72) v1(36.68,27.82) v1(37.69,27.83) v1(39.78,40.64) v1(39.79,39.61) v1(39.78,35.46) v1(39.79,34.43) v1(40.57,44.22) v1(40.57,43.09) v1(42.24,41.86) v1(42.8,44.73) v1(42.8,43.69) v1(43.37,41.87) v1(43.94,44.7) v1(43.95,43.65) v1(44.57,41.87) v1(46.42,40.71) v1(46.43,39.67) v1(46.37,35.45) v1(46.38,34.41) v1(46.49,46.6) v1(46.47,44.44) v1(47.69,46.6) v1(47.66,44.44) v1(48.2,44.21) v1(48.2,43.02) v1(68.58,34.16) v1(69.09,34.16) v1(69.09,33.66) v1(72.41,26.28) v1(72.43,24.73) v1(72.44,23.7) v1(73.45,26.29) v1(73.97,24.26) v1(73.97,23.23) v2(1.98,20.47) v2(9.91,25.65) v2(10.67,19.81) v2(12.45,34.54) v2(12.95,22.1) v2(12.95,12.19) v2(15.49,37.34) v2(18.8,22.1) v2(20.07,40.39) v2(20.07,38.1) v2(21.08,19.81) v2(21.08,16) v2(21.08,12.19) v2(21.34,35.56) v2(21.34,31.75) v2(22.35,40.39) v2(22.35,38.1) v2(23.11,27.69) v2(24.13,22.1) v2(26.92,28.19) v2(26.92,23.88) v2(27.94,19.81) v2(28.96,32.26) v2(32.26,44.2) v2(33.27,42.42) v2(36.07,45.72) v2(36.07,43.18) v2(36.07,38.86) v2(36.43,24.36) v2(36.43,23.6) v2(36.43,22.84) v2(36.43,22.08) v2(36.43,21.32) v2(36.83,31.24) v2(37.19,25.13) v2(37.19,24.36) v2(37.19,23.6) v2(37.19,22.84) v2(37.19,22.08) v2(37.59,35.05) v2(37.95,25.13) v2(37.95,24.36) v2(37.95,23.6) v2(37.95,22.84) v2(37.95,22.08) v2(39.88,45.72) v2(41.4,30.73) v2(43.75,34.96) v2(43.81,33.4) v2(43.87,38.58) v2(44.7,19.56) v2(44.96,24.89) v2(44.96,8.13) v2(44.96,4.32) v2(46.48,36.83) v2(48.26,8.13) v2(48.26,4.32) v2(51.56,8.13) v2(51.56,4.32) v2(51.82,33.78) v2(51.82,29.72) v2(52.58,24.89) v2(52.58,19.56) v2(54.1,37.08) v2(59.94,8.13) v2(59.94,4.32) v2(60.71,24.89) v2(61.47,20.07) v2(61.98,43.18) v2(64.01,17.53) v2(65.79,20.07) v2(66.04,24.89) v2(68.07,7.11) v2(68.07,4.32) v2(68.58,18.03) v2(72.9,18.03) v2(74.68,3.56) v2(75.51,28.83) v2(75.46,18.39) v2(76.15,28.83) v2(76.07,18.39) v2(76.73,18.39) v2(76.81,28.83) v2(78.87,31.5) v2(78.87,30.73) v2(78.99,34.29) v2(79.5,34.29) v2(80.01,28.93) v2(80.14,18.11) v2(80.7,28.93) v2(80.8,18.14) v2(81.43,28.91) v2(81.56,18.16) v2(81.79,31.5) v2(81.79,30.99) v2(81.79,30.48) v2(82.3,32.51) v2(82.3,32) v2(82.3,31.5) v2(82.3,30.99) v2(82.3,30.48)
VBUS: length 18.9
  TOP w0.152: 69.47,30.05 D6.2 68.66,30.73 ; P2.B9 76.46,22.22 v1(76.33,22.35) 75.92,22.35 75.81,22.47 P2.A4
  TOP w0.229: P2.A9 76.28,24.97 76.53,24.72 P2.B4 v1(77.5,24.72)
  TOP w0.305: P1.A4 v2(1.96,22.34) ; P1.A9 v2(1.95,24.84)
  BOTTOM w0.254: 65.77,30.63 U8.1 66.08,31.05 ; 81.41,34.98 C25.1 ; C25.1 82.22,34.29 ; C25.1 80.59,34.29 ; C25.1 81.41,33.6 ; U8.8 66.23,32.95 66.29,33.02 ; 67.69,31.93 C35.1 ; C35.1 67.69,30.56 ; C35.1 68.5,31.24 ; C35.1 66.67,31.24
  BOTTOM w0.305: P1.A9 v2(1.95,24.84) ; P1.A4 v2(1.96,22.34) ; C17.1 v2(10.19,26.8)
  BOTTOM w0.381: U2.1 80.33,33.34 80.39,33.4 ; U2.8 80.45,35.24 80.52,35.31
  vias: v2(68.58,29.97) v2(68.58,29.34) v2(68.58,28.57) v2(68.58,27.94) v2(69.6,29.97) v2(69.6,29.34) v2(69.6,28.57) v2(69.6,27.94) v2(81.67,35.8) v2(81.67,35.16) v2(81.66,33.27) v2(82.31,39.1) v2(82.31,38.47) v2(82.31,37.83) v2(82.31,37.2) v2(82.31,36.56) v2(82.31,35.8) v2(82.31,35.16) v2(82.31,34.53) v2(82.31,33.89) v2(82.31,33.26)
2P5VCC: length 14.5
  TOP w0.381: R39.2 v1(77.98,30.23)
  TOP w0.508: J4.2 76.72,31.1 R39.2
  BOTTOM w0.152: 75.18,31.7 J4.2 ; J4.2 76.12,32.64 ; J4.2 74.24,32.64 ; J4.2 75.18,33.58 ; 75.64,36.58 C26.1 ; C26.1 76.45,37.26 ; C26.1 76.45,35.89 ; C26.1 77.27,36.58 ; C24.1 75.49,36.58 ; C24.1 74.68,35.89 ; C24.1 74.68,37.26
  BOTTOM w0.381: R36.1 77.47,30.73 v1(77.98,30.23)
3P3VCC: length 20.9
  TOP w0.305: 62.47,33.84 R55.2 62.04,34.29 ; J6.1 64.39,29.77 ; J6.1 65.33,28.83 ; J6.1 63.45,28.83 ; J6.1 64.39,27.89 ; C34.1 61.65,33.15 ; C34.1 60.02,33.15 ; C34.1 60.83,33.83 ; C34.1 60.83,32.46 ; 61.94,32.13 R56.1 ; R56.1 62.75,33.13 ; R56.1 63.56,32.13 ; R56.1 62.75,31.13
  BOTTOM w0.305: 63.97,32.95 U8.5 64.27,33.38 ; 61.54,34.04 C36.1 ; C36.1 62.36,33.35 ; C36.1 62.36,34.72 ; C36.1 63.17,34.04 ; J6.1 65.33,28.83 ; J6.1 64.39,29.77 ; J6.1 64.39,27.89 ; J6.1 63.45,28.83 ; 63.92,33.4 L2.2 63.35,34.92
1044_VCC: length 38.9
  TOP w0.229: v2(38.62,19.58) 38.61,19.59 U1.28 ; v2(35.28,20.49) 35.28,20.55 35.31,20.57 U1.20 ; U1.1 v2(38.92,26.11) ; U3.10 42.49,45.65 v2(41.86,46.28) ; U1.6 v2(36.61,26.99)
  TOP w0.254: R51.1 v2(18.91,36.71)
  TOP w0.305: R24.2 v2(48.19,26.34) ; 71.7,32.64 J4.1 ; J4.1 72.64,33.58 ; J4.1 73.58,32.64 ; J4.1 72.64,31.7 ; R25.2 v2(54.84,26.69) ; R49.2 v2(56.82,44.78) ; R29.2 24.47,31.58 v2(24.89,32) ; R35.2 v2(16.13,10.47) ; R20.2 v2(55.19,12.38) ; v2(40.28,38.66) 40.52,38.9 U6.12 ; R30.2 31.56,31.63 v2(31.97,32.04) ; v2(49.05,45.21) 49.36,44.9 R58.2 ; U7.12 v2(40.21,33.69) ; R19.2 v2(55.17,2.69)
  L4_PWR w0.305: 72.64,31.76 J4.1 ; J4.1 73.52,32.64 ; J4.1 71.77,32.64 ; J4.1 72.64,33.52
  BOTTOM w0.305: J4.1 73.58,32.64 ; J4.1 72.64,31.7 ; J4.1 71.7,32.64 ; J4.1 72.64,33.58 ; R4.1 v2(38.28,10.65) ; R8.1 v2(38.28,5.57) ; C23.1 C20.1 38.31,19.89 38.62,19.58 v2(38.62,19.58) ; C21.1 38.86,26.17 v2(38.92,26.11) ; R9.1 v2(38.28,4.3) ; R5.1 v2(38.28,9.38) ; R42.1 41.86,45.43 v2(41.86,46.28) ; C19.1 C22.1 35,20.21 v2(35.28,20.49) ; C18.1 36.35,26.72 v2(36.61,26.99) ; R26.2 v2(45.78,19.08) ; R3.1 v2(38.28,11.92) ; R10.1 v2(38.28,3.03) ; R7.1 v2(38.28,6.84) ; R6.1 v2(38.28,8.11)
  vias: v2(18.92,37.34) v2(71.12,33.66) v2(71.12,32.89) v2(71.12,32) v2(71.12,31.11) v2(71.12,30.23) v2(71.12,29.46) v2(73.28,31.11) v2(73.28,30.23) v2(73.28,29.46)
1044_VCC33: length 8.5
  TOP w0.254: v2(20.56,36.71) R38.1 19.81,37.21
  TOP w1.016: J6.2 66.93,29.97 66.03,30.87 R56.2
  L3_PWR w0.762: J6.2 66.93,29.97 ; J6.2 67.69,28.83 ; J6.2 66.04,28.83 ; J6.2 66.93,28.07
  vias: v2(20.57,37.34)
AUXN: length 48.8
  TOP w0.127: R2.1 v2(36.52,15.13) ; v1(29.64,15.93) 29.51,16.05 25.79,16.05 24.77,17.07 23.71,17.07 v1(23.56,16.92) ; v1(21.11,23.11) 20.98,23.24 7.77,23.24 6.72,22.18 2.75,22.18 v1(2.51,22.43)
  TOP w0.152: R2.1 37.09,15.66 37.41,15.97 U1.25
  BOTTOM w0.127: v1(21.11,23.11) 21.13,23.11 21.26,23.24 21.58,23.24 22.15,22.67 22.15,17.61 22.74,17.03 23.45,17.03 v1(23.56,16.92) ; v1(29.64,15.93) 29.79,16.08 35.48,16.08 36.43,15.13 v2(36.52,15.13) ; v1(2.51,22.43) 2.1,22.84 P1.B8
AUXP: length 48.8
  TOP w0.127: P1.A8 3.44,24.34 3.63,24.54 4.9,24.54 5.28,24.92 6.6,24.92 8,23.52 20.98,23.52 v1(21.11,23.65) ; v1(23.53,17.45) 23.63,17.35 24.89,17.35 25.91,16.33 29.51,16.33 v1(29.64,16.46)
  TOP w0.152: U1.24 37.01,18.49 v1(36.91,18.39)
  BOTTOM w0.127: v1(21.11,23.65) 21.23,23.52 21.69,23.52 22.43,22.78 22.43,17.73 22.85,17.31 23.41,17.31 23.53,17.44 v1(23.53,17.45) ; v1(29.64,16.46) 29.74,16.36 35.46,16.36 35.66,16.56 35.66,17.68 35.79,17.81 36.07,17.81 36.2,17.68 36.2,16.97 36.32,16.84 R1.1
  BOTTOM w0.152: v1(36.91,18.39) 36.86,18.34 36.86,17.51 37.01,17.36 R1.1
C_CC1: length 59.2
  TOP w0.127: v1(76.28,24.41) 76.12,24.26 76.12,23.09 76,22.97 P2.A5 ; U3.4 45.94,44.65 46.28,44.98 46.76,44.98 v1(46.91,44.83)
  BOTTOM w0.127: v1(76.28,24.41) 76.12,24.41 76.05,24.49 74.28,24.49 73.94,24.83 73.94,26.66 73.24,27.36 71.68,27.36 70.13,25.81 62.37,25.81 59.92,28.26 59.92,44.79 59.35,45.36 51.56,45.36 50.34,44.14 50.34,43.63 49.05,42.34 47.31,42.34 46.99,42.66 46.99,44.75 v1(46.91,44.83) 46.72,45.02 R43.2
C_CC2: length 59.2
  TOP w0.127: U3.5 45.68,45.05 46,45.36 47.29,45.36 47.42,45.24 47.42,44.86 v1(47.4,44.83)
  TOP w0.152: v1(77.5,24.21) P2.B5
  BOTTOM w0.127: R44.2 47.59,45.02 v1(47.4,44.83) 47.27,44.7 47.27,42.77 47.42,42.62 48.93,42.62 50.06,43.75 50.06,44.25 51.45,45.64 59.46,45.64 60.2,44.91 60.2,28.37 62.48,26.09 70.01,26.09 71.56,27.64 73.36,27.64 74.22,26.77 74.22,24.94 74.4,24.77 76.58,24.77 77.14,24.21 v1(77.5,24.21)
C_DRX1N: length 33.1
  TOP w0.127: U1.31 39.17,21.75 40.07,21.75 41.12,20.7 58.69,20.7 60.87,18.52 62.2,18.52 63.25,19.56 64.34,19.56 65.3,18.59 66.31,18.59 68.08,20.37 68.99,20.37 C15.1
C_DRX1P: length 33.1
  TOP w0.127: C16.1 68.99,20.09 68.2,20.09 66.42,18.31 65.19,18.31 64.22,19.28 63.36,19.28 62.32,18.24 60.76,18.24 58.57,20.42 41.01,20.42 39.96,21.47 39.17,21.47 U1.30
C_DRX2N: length 35.5
  TOP w0.127: C10.1 69.02,25.55 68.01,25.55 66.84,26.72 65.46,26.72 63.81,25.07 62,25.07 60.55,26.52 58.6,26.52 57.15,25.07 54.35,25.07 53.21,26.21 51.79,26.21 50.65,25.07 46.8,25.07 45.5,26.37 44.7,26.37 43.41,25.07 42.53,25.07 41.49,26.11 41.05,26.11 40.01,25.07 39.17,25.07 U1.39
C_DRX2P: length 35.5
  TOP w0.127: C9.1 68.99,25.83 68.12,25.83 66.95,27 65.34,27 63.69,25.35 62.12,25.35 60.67,26.8 58.48,26.8 57.04,25.35 54.47,25.35 53.33,26.49 51.67,26.49 50.53,25.35 46.91,25.35 45.62,26.64 44.59,26.64 43.29,25.35 42.65,25.35 41.61,26.39 40.93,26.39 39.89,25.35 39.17,25.35 U1.40
C_DTX1N: length 35.5
  TOP w0.127: U1.34 39.17,22.95 40.19,22.95 41.33,21.82 43.47,21.82 44.6,22.95 45.76,22.95 46.84,21.87 47.53,21.87 48.62,22.95 50.26,22.95 51.17,22.04 52.28,22.04 53.2,22.95 54.94,22.95 56.12,21.77 58.33,21.77 59.51,22.95 61.12,22.95 62.66,21.41 64.27,21.41 65.81,22.95 66.79,22.95 67.92,21.82 68.99,21.82 C13.1
C_DTX1P: length 35.5
  TOP w0.127: U1.33 39.17,22.67 40.08,22.67 41.21,21.54 43.59,21.54 44.72,22.67 45.64,22.67 46.72,21.59 47.65,21.59 48.73,22.67 50.14,22.67 51.05,21.76 52.4,21.76 53.31,22.67 54.82,22.67 56.01,21.49 58.45,21.49 59.63,22.67 61.01,22.67 62.55,21.13 64.39,21.13 65.93,22.67 66.67,22.67 67.8,21.54 68.99,21.54 C14.1
C_DTX2N: length 30.3
  TOP w0.127: U1.36 39.17,23.87 67.08,23.87 67.28,24.08 69.02,24.08 C12.1
C_DTX2P: length 30.3
  TOP w0.127: C11.1 69.02,24.36 67.17,24.36 66.96,24.15 39.17,24.15 U1.37
C_SBU1: length 56.8
  TOP w0.127: v1(47.83,43.36) 47.83,43.39 47.7,43.52 45.67,43.52 45.34,43.18 44.88,43.18 44.76,43.3 U3.1
  TOP w0.152: P2.A8 74.73,24.47 74.57,24.62 v1(74.57,25.12)
  BOTTOM w0.127: v1(47.83,43.36) 47.83,43.38 47.96,43.51 48.45,43.51 51.14,46.2 59.62,46.2 60.81,45.02 60.81,28.84 63,26.64 69.82,26.64 71.25,28.07 73.75,28.07 75.13,26.68 75.13,26.34 74.78,25.99 74.78,25.76 74.91,25.63 75.13,25.63 75.49,25.98 75.83,25.98 76.07,25.75 76.07,25.34 75.92,25.2 74.65,25.2 v1(74.57,25.12)
C_SBU2: length 56.8
  TOP w0.127: v1(47.85,43.92) 47.73,43.79 44.81,43.79 U3.2 ; P2.B8 v1(77.52,22.72)
  BOTTOM w0.127: v1(77.52,22.72) 77.56,22.72 77.85,23.01 77.85,24.84 77.84,24.85 77.84,24.86 77.64,25.06 77.63,25.06 77.22,25.48 76.73,25.48 73.86,28.35 71.13,28.35 69.71,26.92 63.12,26.92 61.09,28.96 61.09,45.14 59.74,46.48 51.03,46.48 48.34,43.79 47.98,43.79 v1(47.85,43.92)
CC1: length 53.9
  TOP w0.127: v1(12.12,30.23) 11.96,30.38 11.96,32.07 19.12,39.22 28.64,39.22 34.13,44.71 41.58,44.71 41.64,44.65 U3.12 42.16,44.65
  TOP w0.152: P1.A5 3.47,22.84 3.61,22.71 4.83,22.71 v1(5.82,23.7)
  BOTTOM w0.127: v1(5.82,23.7) 5.94,23.83 9.53,23.83 11.96,26.26 11.96,30.07 v1(12.12,30.23)
CC2: length 54
  TOP w0.127: 42.16,45.05 U3.11 41.64,45.05 41.58,44.99 34.01,44.99 28.52,39.5 19,39.5 11.68,32.18 11.68,30.35 v1(11.56,30.23)
  BOTTOM w0.127: v1(11.56,30.23) 11.68,30.1 11.68,26.38 9.41,24.1 5.94,24.1 v1(5.82,24.23)
  BOTTOM w0.152: P1.B5 2.53,24.34 2.72,24.16 3.12,24.16 3.58,24.61 5.59,24.61 5.82,24.38 v1(5.82,24.23)
CD1: length 6.7
  TOP w0.152: U6.13 40.86,38.4 v2(40.49,38.02) 39.83,38.02 39.37,38.48 v2(39.37,42.11)
  BOTTOM w0.152: v2(39.37,42.11) 39.34,42.14 R67.1
CD2: length 6.7
  TOP w0.152: v2(39.7,37.01) 39.7,36.09 39.17,35.56 39.17,34.04 40.01,33.19 U7.13
  BOTTOM w0.152: R73.1 v2(39.7,37.01)
CFG0: length 13.6
  TOP w0.152: JMP7.2 33.78,35.18 36.2,35.18 39.45,31.93 39.45,28.63 37.81,26.99 U1.3
CFG1: length 21.3
  TOP w0.152: JMP6.2 28.01,33.78 36.32,33.78 38.18,31.93 v1(38.18,29.54)
  BOTTOM w0.152: R66.1 35.47,26.13 35.47,26.66 36.27,27.46 37.9,27.46 38.27,27.83 38.27,28.95 R64.1 38.18,29.53 v1(38.18,29.54)
CFG1_UTX1N: length 39.5
  TOP w0.127: v1(37.47,28.27) 37.35,28.15 37.35,27.47 37.35,27.47 37.35,26.17 U1.4 ; C30.2 6.35,21.36 v1(6.38,21.38)
  BOTTOM w0.127: v1(37.47,28.27) 37.44,28.27 37.31,28.4 37.31,28.72 R64.2 36.86,29.79 23.23,29.79 14.26,20.83 6.51,20.83 6.38,20.96 v1(6.38,21.38)
CTL0/SDA: length 24.2
  TOP w0.152: U1.22 36.21,19.27 35.81,18.87 35.81,17.22 32.41,13.82 30.84,13.82 J1.2 28.83,9.27 28.83,6.99 v2(31.52,4.3)
  TOP w0.241: SW1.7 v2(31.52,4.3)
  BOTTOM w0.152: R17.1 v2(31.52,4.3)
CTL1: length 20.5
  TOP w0.152: U1.23 36.61,19.09 36.3,18.77 36.3,16.93 32.26,12.89 31.69,12.89 29.97,11.18 29.97,7.06 31.47,5.57 v2(31.56,5.57)
  TOP w0.241: SW1.6 v2(31.56,5.57)
  BOTTOM w0.152: R16.1 v2(31.56,5.57)
DC_BOOST1: length 16.4
  TOP w0.152: JMP11.2 57.48,42.42 48.77,42.42 47.62,41.27 47.62,40.26 46.56,39.19 45.8,39.19 45.59,39.4 U6.4
DC_BOOST2: length 12.5
  TOP w0.152: U7.4 45.62,34.19 45.92,33.88 47.8,33.88 51.05,37.13 51.05,40 JMP1.2
DDM1: length 50.7
  TOP w0.127: U6.6 44.86,40.31 45.92,40.31 v1(46,40.39) ; U3.20 44.16,42.33 v1(44.27,42.21)
  TOP w0.152: v1(74.38,23.95) 74.73,23.95 74.78,23.9 75.34,23.9 P2.A7
  BOTTOM w0.127: v1(44.27,42.21) 44.13,42.08 44.13,41.47 44.25,41.35 44.73,41.35 44.86,41.22 44.86,41.02 44.57,40.74 44.57,40.56 44.79,40.34 45.95,40.34 v1(46,40.39) 46.05,40.34 46.93,40.34 47.45,39.82 47.45,38.29 49.32,36.42 58.06,36.42 59.44,35.05 59.44,25.27 62.1,22.61 72.35,22.61 73.59,23.85 74.27,23.85 v1(74.38,23.95) 74.71,23.95 74.76,24 R69.1
DDM2: length 52.8
  TOP w0.127: U7.6 44.86,35.08 45.85,35.08 v1(45.97,35.2) ; U3.17 42.96,42.34 v1(43.05,42.24)
  BOTTOM w0.127: R72.1 74.96,22.57 74.31,22.57 73.48,21.74 61.08,21.74 58.47,24.35 58.47,34.39 57.78,35.08 46.1,35.08 v1(45.97,35.2) 45.87,35.1 45.4,35.1 45.09,35.42 45.09,37.59 44.62,38.06 43.7,38.06 42.95,38.81 42.95,40.46 43.36,40.87 43.36,41.12 43.23,41.25 43.08,41.25 42.95,41.38 42.95,42.14 43.05,42.24 v1(43.05,42.24)
DDP1: length 50.7
  TOP w0.127: v1(43.71,42.24) 43.76,42.28 U3.19 ; U6.5 44.91,40.03 45.9,40.03 v1(46,39.93)
  TOP w0.152: P2.A6 75.35,23.52 74.78,23.52 74.73,23.47 v1(74.37,23.47)
  BOTTOM w0.127: R70.1 74.83,23.37 74.73,23.47 v1(74.37,23.47) 74.27,23.57 73.71,23.57 72.47,22.33 61.99,22.33 59.16,25.16 59.16,34.94 57.95,36.14 49.2,36.14 47.17,38.18 47.17,39.7 46.81,40.06 46.13,40.06 v1(46,39.93) 45.87,40.06 44.68,40.06 43.85,40.88 43.85,42.1 v1(43.71,42.24)
DDP2: length 52.8
  TOP w0.127: v1(42.55,42.27) 42.56,42.28 U3.16 ; v1(45.97,34.7) 45.87,34.8 44.86,34.8 U7.5
  BOTTOM w0.127: R71.1 74.99,22.29 74.43,22.29 73.6,21.46 60.96,21.46 58.19,24.23 58.19,34.28 57.67,34.8 46.08,34.8 v1(45.97,34.7) 45.95,34.7 45.82,34.82 45.29,34.82 44.81,35.31 44.81,37.48 44.5,37.78 43.58,37.78 42.67,38.7 42.67,42.14 v1(42.55,42.27)
DEQ0: length 22.4
  TOP w0.152: U1.38 v1(39.69,24.61)
  BOTTOM w0.152: JMP3.2 55.28,17.65 53.47,17.65 50.36,20.76 42.67,20.76 40.47,22.96 39.93,22.96 39.55,23.34 39.55,24.43 39.69,24.57 v1(39.69,24.61)
DEQ1: length 23.9
  TOP w0.152: v1(39.8,20.9) 39.7,21.01 U1.29
  BOTTOM w0.152: v1(39.8,20.9) 39.91,21.01 41.24,21.01 56,6.26 JMP2.2
DIR0: length 31
  TOP w0.241: SW1.5 v2(31.52,6.84)
  BOTTOM w0.152: R61.1 28.06,26.01 31.75,26.01 34.09,23.67 34.09,22.05 33.73,21.69 32.54,21.69 27.69,16.84 27.69,15.37 29.21,13.84 29.21,9.15 v2(31.52,6.84) R15.1
DIR0_URX1P: length 36.9
  TOP w0.127: v1(28.4,26.62) 28.53,26.75 30.78,26.75 30.95,26.58 35.72,26.58 35.81,26.49 U1.8
  BOTTOM w0.127: 28.4,26.62 v1(28.4,26.62) 28.34,26.69 R61.2 27.86,26.77 22.27,26.77 15.39,19.89 15.39,16.75 14.7,16.05 12.89,16.05 10.58,18.36 9.68,18.36 9.5,18.19 9.5,17.53 9.17,17.2 7.8,17.2 R53.2
DIR1: length 21.9
  TOP w0.152: v1(30.73,11.3) 30.73,8.93 v2(31.56,8.11)
  TOP w0.241: SW1.4 v2(31.56,8.11)
  BOTTOM w0.152: R65.1 35.18,21.72 34.16,20.7 32.89,20.7 28.85,16.66 28.85,15.72 30.73,13.84 v1(30.73,11.3) ; R14.1 v2(31.56,8.11)
DRX1N: length 8.3
  TOP w0.127: P2.B10 77,21.68 76.91,21.59 76.48,21.59 arc(76.19,21.47) 76.07,21.18 76.07,20.9 arc(76.05,20.79) 75.98,20.69 75.92,20.62 arc(75.61,20.42) 75.25,20.35 71.64,20.35 U4.7 71.42,20.35 70.87,20.35 U4.4 70.68,20.37 70,20.37 C15.2
DRX1P: length 8.3
  TOP w0.127: P2.B11 76.91,21.31 76.48,21.31 arc(76.39,21.27) 76.35,21.18 76.35,20.9 arc(76.31,20.68) 76.18,20.49 76.12,20.43 arc(75.72,20.16) 75.24,20.07 71.64,20.07 U4.6 71.42,20.07 70.87,20.07 U4.5 70.62,20.09 70,20.09 C16.2
DRX2N: length 5.9
  TOP w0.127: P2.A10 75.29,25.58 71.64,25.58 U5.4 71.42,25.58 70.87,25.58 U5.7 70.65,25.58 70.05,25.58 C10.2
DRX2P: length 5.9
  TOP w0.127: P2.A11 75.29,25.86 71.64,25.86 U5.5 71.42,25.86 70.87,25.86 U5.6 70.65,25.86 70.02,25.86 C9.2
DTX1N: length 5.9
  TOP w0.127: C13.2 70,21.82 70.62,21.82 U4.1 70.86,21.86 71.43,21.86 U4.10 71.63,21.86 75.29,21.86 P2.A3
DTX1P: length 5.9
  TOP w0.127: C14.2 70,21.54 70.68,21.54 U4.2 70.86,21.55 71.43,21.55 U4.9 71.64,21.56 75.31,21.56 P2.A2
DTX2N: length 11.1
  TOP w0.127: v1(73.14,26.69) 73.27,26.82 75.72,26.82 arc(75.85,26.79) 75.97,26.72 75.97,26.71 arc(76.07,26.56) 76.11,26.38 76.11,25.76 arc(76.14,25.62) 76.22,25.5 76.28,25.44 arc(76.42,25.35) 76.57,25.33 76.89,25.33 P2.B3 ; v1(72.03,24.01) 71.95,24.08 71.65,24.08 U5.1 71.42,24.08 70.87,24.08 U5.10 70.65,24.08 70.02,24.08 C12.2
  BOTTOM w0.127: v1(73.14,26.69) 73.08,26.62 73.08,24.46 72.72,24.1 72.13,24.1 v1(72.03,24.01)
DTX2P: length 11.1
  TOP w0.127: 75.78,27.1 75.75,27.1 ; 75.75,27.1 73.05,27.1 72.69,26.75 v1(72.69,26.68) ; 75.75,27.1 arc(75.93,27.06) 76.08,26.96 76.17,26.87 arc(76.33,26.64) 76.39,26.36 76.39,25.84 arc(76.41,25.73) 76.47,25.64 arc(76.52,25.62) 76.57,25.61 76.89,25.61 P2.B2 ; v1(72.03,24.44) 72,24.41 71.59,24.41 U5.2 71.47,24.41 70.82,24.41 U5.9 70.75,24.47 70.66,24.38 70,24.38 C11.2
  BOTTOM w0.127: v1(72.03,24.44) 72.08,24.38 72.6,24.38 72.8,24.58 72.8,26.58 v1(72.69,26.68)
EN: length 2.1
  TOP w0.241: SW1.1 v2(31.52,11.92)
  BOTTOM w0.152: R11.1 v2(31.52,11.92)
EQ1: length 50.8
  TOP w0.152: v2(43.83,36.8) 43.83,37.65 U6.1
  BOTTOM w0.152: v2(43.83,36.8) 43.28,36.26 43.28,33.2 43.69,32.79 46.3,32.79 47.37,33.86 50.6,33.86 52.68,31.78 52.68,26.34 56.64,22.38 56.64,22.35 62.48,16.51 68.33,16.51 70.36,14.48 70.36,11.94 71.12,11.18 72.9,11.18 JMP10.1
EQ2: length 34.8
  TOP w0.152: U7.1 v2(43.78,31.67)
  BOTTOM w0.152: JMP12.1 63.75,13.21 61.98,13.21 61.44,13.74 61.44,16.89 52.27,26.06 52.27,30.1 51.26,31.11 44.34,31.11 v2(43.78,31.67)
FLIP/SCL: length 38.6
  TOP w0.152: J2.2 23.05,10.54 26.99,14.48 32.44,14.48 35.36,17.4 35.36,19.08 35.81,19.53 U1.21
  TOP w0.241: SW1.8 v2(31.56,3.03)
  BOTTOM w0.152: R68.1 20.02,7.57 J2.2 24.89,8.64 28.45,8.64 31.11,5.97 31.11,3.56 31.56,3.11 v2(31.56,3.03) R18.1
HPDIN: length 12.7
  TOP w0.152: U1.32 v1(39.7,22.21)
  BOTTOM w0.152: v1(39.7,22.21) 40.58,22.21 47.05,15.74 J3.2
I2C_EN: length 20.9
  TOP w0.152: v1(33.71,22.22) 34.76,22.22 34.76,22.21 U1.17
  BOTTOM w0.152: v1(33.71,22.22) 32.18,22.22 25.09,15.12 20.49,15.12 19.41,14.04 JMP9.2
SBU1: length 34.4
  TOP w0.127: v1(40.92,43.41) 40.96,43.45 U3.15
  TOP w0.152: v1(38.4,18.39) 38.21,18.58 U1.27
  BOTTOM w0.127: v1(40.92,43.41) 40.82,43.51 40.39,43.51 40.18,43.31 40.18,42.37 41.17,41.38 41.17,33.23 40.49,32.55 40.49,26.4 39.22,25.13 39.22,20.4 39.35,20.27 39.35,19.04 38.7,18.39 v1(38.4,18.39)
  BOTTOM w0.152: R1.2 38.06,16.84 39.24,16.84 39.52,17.12 39.52,17.53 39.24,17.81 38.53,17.81 38.4,17.93 v1(38.4,18.39)
SBU2: length 34.4
  TOP w0.127: v1(40.92,43.92) 40.99,43.85 U3.14
  TOP w0.152: U1.26 v1(37.81,18.82) 37.81,15.96 38.13,15.64 R2.2
  BOTTOM w0.127: v1(40.92,43.92) 40.79,43.79 40.27,43.79 39.9,43.42 39.9,42.25 40.89,41.26 40.89,33.35 40.21,32.66 40.21,26.51 38.94,25.24 38.94,20.28 39.07,20.15 39.07,19.33 38.56,18.82 v1(37.81,18.82)
SLP_S0#: length 29.7
  TOP w0.241: SW1.3 v2(31.52,9.38)
  BOTTOM w0.152: R13.1 v2(31.52,9.38) 31.11,9.38 29.72,10.77 29.72,13.84 28.04,15.52 28.04,16.76 32.64,21.36 33.88,21.36 34.39,21.87 34.39,23.83 30.38,27.84 28.06,27.84 R62.1
SLP_URX1N: length 36.9
  TOP w0.127: v1(28.38,27.11) 28.45,27.03 30.89,27.03 31.07,26.86 35.98,26.86 36.21,26.63 U1.7
  BOTTOM w0.127: v1(28.38,27.11) 28.32,27.05 28.05,27.05 R62.2 27.83,27.05 22.16,27.05 15.11,20.01 15.11,16.87 14.58,16.33 13,16.33 10.69,18.64 10.06,18.64 9.45,19.25 7.8,19.25 R54.2
SWAP: length 27.3
  TOP w0.241: SW1.2 v2(31.56,10.65)
  BOTTOM w0.152: R12.1 v2(31.56,10.65) 30.63,10.65 30.23,11.05 30.23,13.84 28.48,15.59 28.48,16.72 32.79,21.03 34.04,21.03 34.75,21.74 34.75,24.08 34.24,24.59 34.24,28.5 34.77,29.03 R63.1
SWAP_UTX1P: length 39.5
  TOP w0.127: v1(36.88,28.24) 36.94,28.24 37.07,28.12 37.07,27.47 37.07,27.47 37.07,26.17 U1.5 ; v1(6.4,19.28) 6.37,19.26 C31.2
  BOTTOM w0.127: v1(36.88,28.24) 37.01,28.37 37.01,28.72 R63.2 36.79,29.12 36.79,29.3 36.58,29.51 23.34,29.51 14.38,20.55 6.53,20.55 6.4,20.42 6.4,19.29 v1(6.4,19.28)
U2_PG: length 4.9
  TOP w0.152: v1(79,35.94) 77.98,34.92 R39.1
  BOTTOM w0.152: U2.6 v1(79,35.94)
U2_SW: length 2.5
  BOTTOM w0.152: U2.7 79.5,36.74 L1.1
U8_PG: length 2.2
  TOP w0.254: v1(64.77,33.65) 64.77,33.66 64.14,33.66 63.51,34.28 R55.1
  BOTTOM w0.152: U8.6 v1(64.77,33.65)
U8_SW: length 4
  BOTTOM w0.203: L2.1 66.12,35.6 v1(65.41,36.32)
  BOTTOM w0.254: L2.1 65.27,34.07 U8.7
UDM1: length 52.4
  TOP w0.127: P1.A7 1.04,23.75 3.53,23.75 v1(3.63,23.85) ; U6.9 41.24,40.31 40.24,40.31 v1(40.16,40.4)
  BOTTOM w0.127: v1(3.63,23.85) 3.73,23.75 4.37,23.75 5.21,22.91 9.5,22.91 13.03,26.44 13.03,33.71 18.69,39.37 29.83,39.37 30.75,40.28 40.05,40.28 v1(40.16,40.4)
UDM2: length 54
  TOP w0.127: v1(40.14,35.19) 40.23,35.1 41.22,35.1 U7.9
  BOTTOM w0.127: v1(40.14,35.19) 39.98,35.03 39.12,35.03 38.81,34.72 38.81,34.52 38.96,34.37 39.19,34.37 39.37,34.19 39.37,33.68 39.17,33.48 37.53,33.48 34.89,30.84 24.01,30.84 20.66,34.19 17.31,34.19 14.43,31.3 14.43,26.1 10.15,21.82 3.97,21.82 2.34,23.45 1.06,23.45 P1.B7
UDP1: length 52.4
  TOP w0.127: P1.A6 1.05,23.44 3.56,23.44 v1(3.63,23.37) ; U6.10 41.24,39.98 40.24,39.98 v1(40.16,39.9)
  BOTTOM w0.127: v1(3.63,23.37) 3.73,23.47 4.24,23.47 5.08,22.63 9.62,22.63 13.31,26.33 13.31,33.59 18.81,39.09 29.95,39.09 30.86,40.01 40.05,40.01 v1(40.16,39.9)
UDP2: length 54
  TOP w0.127: U7.10 41.22,34.77 40.23,34.77 v1(40.18,34.72)
  BOTTOM w0.127: P1.B6 1.06,23.73 2.46,23.73 4.09,22.1 10.03,22.1 14.15,26.21 14.15,31.42 17.2,34.47 20.78,34.47 24.13,31.11 34.77,31.11 39.47,35.81 40.11,35.81 40.49,35.43 40.49,34.85 40.36,34.72 v1(40.18,34.72)
UEQ0/A0: length 22.4
  TOP w0.152: JMP5.2 55.2,28.91 v1(51.61,28.91) ; U1.35 40.04,23.41 40.05,23.4 v1(40.12,23.4)
  BOTTOM w0.152: v1(40.12,23.4) 40.12,23.41 49.7,23.41 51.54,25.25 51.54,28.83 v1(51.61,28.91)
UEQ1/A1: length 14.3
  TOP w0.152: JMP4.2 48.59,28.7 45.54,28.7 44.78,29.46 40.79,29.46 38.21,26.88 U1.2
URX1N: length 8.3
  BOTTOM w0.127: R54.1 7.45,18.35 6,18.35 2.61,21.74 1.05,21.74 P1.B10
URX1P: length 8.3
  BOTTOM w0.127: R53.1 7.5,18.06 5.89,18.06 2.49,21.46 1.07,21.46 P1.B11
URX2N: length 2.4
  TOP w0.127: P1.A10 1.06,25.45 2.82,25.45 3.13,25.14 C2.1
URX2P: length 2.4
  TOP w0.127: P1.A11 1.06,25.73 2.83,25.73 3.13,26.03 C1.1
UTX1N: length 5.6
  TOP w0.127: C5.1 C30.1 5.84,20.63 5.71,20.5 4.36,20.5 3.15,21.71 1.08,21.71 P1.A3
UTX1P: length 5.7
  TOP w0.127: C31.1 5.82,20.04 5.64,20.22 4.24,20.22 3.03,21.43 1.04,21.43 P1.A2
UTX2N: length 2.4
  BOTTOM w0.127: C4.1 2.82,25.45 1.06,25.45 P1.B3
UTX2P: length 2.4
  BOTTOM w0.127: P1.B2 1.06,25.73 2.83,25.73 C3.1
VIO_SEL: length 20.1
  TOP w0.152: JMP8.2 23.86,30.37 26.37,27.86 v1(26.37,26.39) ; U1.14 v1(33.71,23.41)
  BOTTOM w0.152: v1(26.37,26.39) 29.35,23.41 v1(33.71,23.41)
N06058: length 1.9
  TOP w0.241: SW1.16 v2(41.21,11.92)
  BOTTOM w0.152: v2(41.21,11.92) R3.2
N06065: length 1.9
  TOP w0.241: SW1.15 v2(41.21,10.65)
  BOTTOM w0.152: v2(41.21,10.65) R4.2
N06072: length 1.9
  TOP w0.241: SW1.14 v2(41.21,9.38)
  BOTTOM w0.152: v2(41.21,9.38) R5.2
N06079: length 1.9
  TOP w0.241: SW1.13 v2(41.21,8.11)
  BOTTOM w0.152: v2(41.21,8.11) R6.2
N06086: length 1.9
  TOP w0.241: SW1.12 v2(41.21,6.84)
  BOTTOM w0.152: v2(41.21,6.84) R7.2
N06093: length 1.9
  TOP w0.241: SW1.11 v2(41.21,5.57)
  BOTTOM w0.152: v2(41.21,5.57) R8.2
N06100: length 1.9
  TOP w0.241: SW1.10 v2(41.21,4.3)
  BOTTOM w0.152: v2(41.21,4.3) R9.2
N06107: length 1.9
  TOP w0.241: SW1.9 v2(41.21,3.03)
  BOTTOM w0.152: v2(41.21,3.03) R10.2
N06374: length 2.6
  TOP w0.152: JMP2.3 56.86,3.77 54.38,3.77 R19.1
N06386: length 2.4
  TOP w0.152: R21.1 JMP2.4
N06671: length 2.5
  TOP w0.152: JMP4.3 49.81,27.38 R24.1
N06683: length 2.3
  TOP w0.152: JMP4.4 R27.1
N06999: length 2.5
  TOP w0.152: JMP3.3 56.95,13.42 R20.1
N07011: length 2.7
  TOP w0.152: R23.1 JMP3.4
N07344: length 2.5
  TOP w0.152: JMP5.3 56.56,27.73 R25.1
N07356: length 2.6
  TOP w0.152: R28.1 JMP5.4
N08045: length 10.1
  TOP w0.254: R38.2 R51.2 18.28,35.68 17.53,34.92 17.53,29.34 16.64,28.45 ; R33.2 16.64,28.45 ; 16.64,28.45 v1(16.64,28.7)
N08061: length 2.6
  TOP w0.254: R33.1 18.13,27.04 JMP8.3
N08073: length 2.4
  TOP w0.152: R34.1 JMP8.4
N08437: length 2.5
  TOP w0.152: JMP9.3 17.79,11.51 R35.1
N08449: length 2.5
  TOP w0.152: R37.1 15.29,14.07 JMP9.4
N08820: length 2.5
  TOP w0.152: JMP7.3 31.23,32.68 R30.1
N08832: length 2.5
  TOP w0.152: R32.1 31.17,35.25 JMP7.4
N09158: length 2.3
  BOTTOM w0.152: R26.1 48.97,18.26 J3.1
N09488: length 2.5
  TOP w0.152: R29.1 24.09,32.63 JMP6.3
N09500: length 1.9
  TOP w0.152: R31.1 JMP6.4
N15413: length 2.2
  TOP w0.152: R41.1 79.6,31.47 80.52,32.38 80.64,32.38
N35354: length 2.3
  TOP w0.152: R47.1 JMP10.4
N35366: length 2
  TOP w0.152: R45.1 JMP10.2
N35378: length 2.4
  TOP w0.152: JMP10.3 74.38,12.23 R46.1
N35403: length 2.8
  TOP w0.152: R48.1 73.57,6.77 JMP10.5
N36817: length 2.7
  TOP w0.152: R49.1 58.67,43.74 JMP11.1
N36900: length 2.3
  TOP w0.152: R50.1 56.17,41.18 JMP11.4
N48828: length 39
  TOP w0.127: C1.2 3.73,25.91 3.89,25.76 4.9,25.76 7.95,28.8 14.12,28.8 15.37,27.56 15.37,26.42 15.87,25.91 21.09,25.91 21.56,26.39 21.56,27.81 22.3,28.55 23.84,28.55 24.54,27.85 24.54,26.38 25,25.91 33.89,25.91 34.46,25.35 35.25,25.35 U1.9
